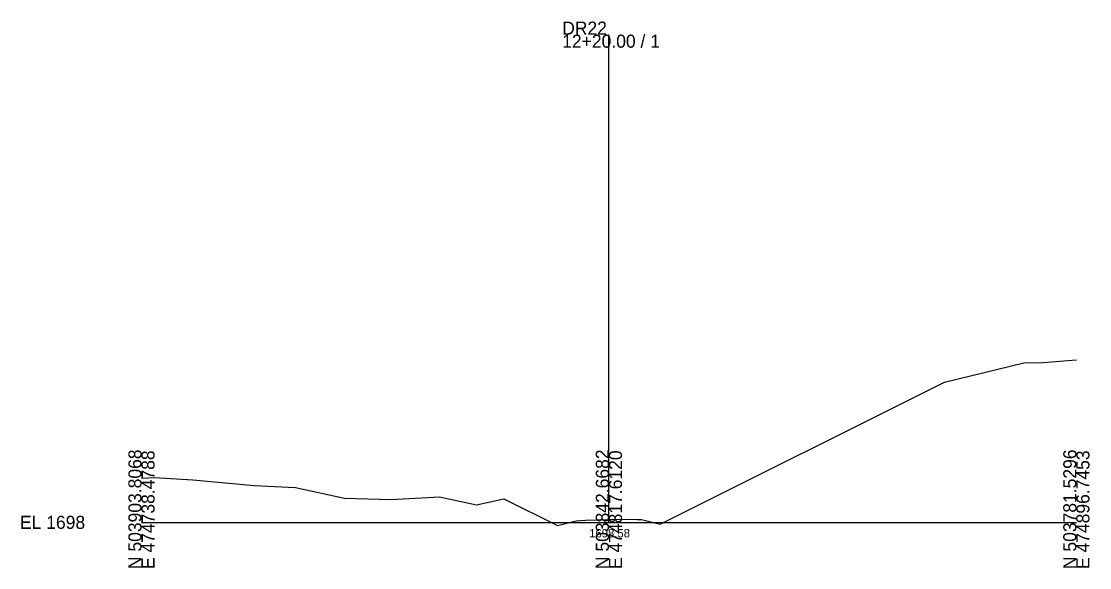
# Model space of a CAD drawing. Extents: x -26 to 1203, y -10 to 9633.
# Drawn here: x -25.7 to 202.8, y 5490.3 to 5607.2 of the extents above; entities that cross this region are included whole.
import ezdxf

# ---------------------------------------------------------------- set-up
doc = ezdxf.new("R2010")
doc.units = 0
for name, color, linetype in [('Exist Cross Section Cell', 7, 'Continuous'), ('Exist XS Center Line Elevation Label', 7, 'Continuous'), ('Exist XS Ground Line', 7, 'Continuous'), ('Scratch_Level_5', 7, 'Continuous')]:
    doc.layers.add(name, color=color, linetype=linetype)

msp = doc.modelspace()

# ---------------------------------------------------------------- linework, layer by layer
at = {"layer": 'Exist Cross Section Cell'}
for p, q in [((100, 5500), (100, 5604.39)), ((0, 5500), (100, 5500)), ((100, 5500), (200, 5500))]:
    msp.add_line(p, q, dxfattribs=at)
at = {"layer": 'Exist XS Ground Line'}
msp.add_lwpolyline([(0, 5509.48), (2.77, 5509.63), (10.98, 5509.13), (24.08, 5507.92), (32.94, 5507.47), (43.42, 5505.15), (53.44, 5504.88), (63.78, 5505.47), (71.66, 5503.73), (77.52, 5505.06), (89, 5499.32), (93, 5500.32), (93.98, 5500.4), (95, 5500.48), (100, 5500.58), (105, 5500.68), (106.02, 5500.64), (107, 5500.6), (111, 5499.6), (171.77, 5529.99), (188.75, 5534.18), (192.9, 5534.2), (200, 5534.8)], dxfattribs=at)
at = {"layer": 'Scratch_Level_5'}
msp.add_lwpolyline([(0, 5509.48), (2.77, 5509.63), (10.98, 5509.13), (24.08, 5507.92), (32.94, 5507.47), (43.42, 5505.15), (53.44, 5504.88), (63.78, 5505.47), (71.66, 5503.73), (77.52, 5505.06), (89, 5499.32), (93, 5500.32), (93.98, 5500.4), (95, 5500.48), (100, 5500.58), (105, 5500.68), (106.02, 5500.64), (107, 5500.6), (111, 5499.6), (171.77, 5529.99), (188.75, 5534.18), (192.9, 5534.2), (200, 5534.8)], dxfattribs=at)

# ---------------------------------------------------------------- texts
at = {"layer": 'Exist Cross Section Cell'}
for s, p in [('DR22', (90, 5604.39)), ('12+20.00 / 1', (90, 5601.59)), ('EL 1698', (-26, 5498.6))]:
    msp.add_text(s, height=2.8, dxfattribs=at).set_placement(p)
for s, p in [('N 503903.8068', (0, 5490)), ('E 474738.4788', (2.8, 5490)), ('N 503842.6682', (100, 5490)), ('E 474817.6120', (102.8, 5490)), ('N 503781.5296', (200, 5490)), ('E 474896.7453', (202.8, 5490))]:
    msp.add_text(s, height=2.8, rotation=90, dxfattribs=at).set_placement(p)
at = {"layer": 'Exist XS Center Line Elevation Label'}
msp.add_text('1698.58', height=1.8, dxfattribs=at).set_placement((95.8, 5496.78))

doc.saveas('drawing.dxf')
